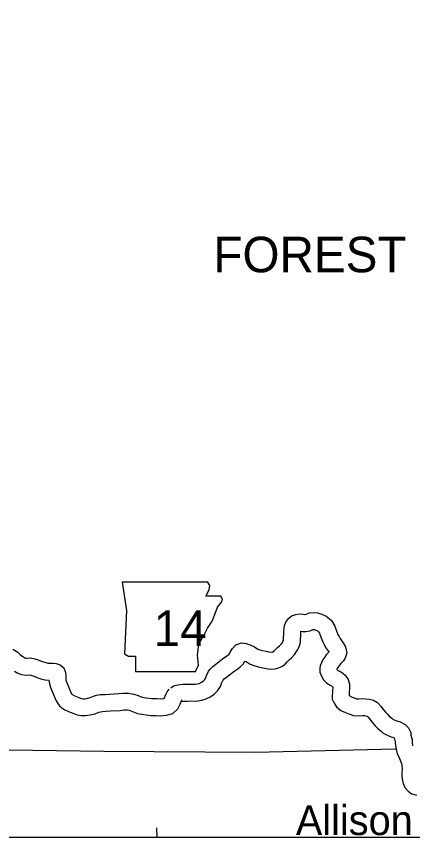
# Model space of a CAD drawing. Extents: x 1377389 to 1380723, y 1168351 to 1170484.
# Drawn here: x 1377764.7 to 1377835.2, y 1169604.3 to 1169750.4 of the extents above; entities that cross this region are included whole.
import ezdxf

# ---------------------------------------------------------------- set-up
doc = ezdxf.new("R2010")
doc.units = 0
doc.layers.add('B_Fill', color=7, linetype='Continuous')
doc.layers.add('B_Text', color=7, linetype='Continuous')

msp = doc.modelspace()

# ---------------------------------------------------------------- linework, layer by layer
at = {"layer": 'B_Fill'}
msp.add_line((1377789.75, 1169604.28), (1377789.7, 1169606.04), dxfattribs=at)
msp.add_lwpolyline([(1377783.57, 1169649.76), (1377784.33, 1169644.68), (1377783.99, 1169636.98), (1377784.67, 1169636.56), (1377785.94, 1169636.56), (1377785.94, 1169633.85), (1377796.6, 1169633.85), (1377797.11, 1169634.95), (1377796.94, 1169636.73), (1377797.19, 1169638.76), (1377798.12, 1169640.37), (1377798.71, 1169641.55), (1377799.56, 1169642.82), (1377800.07, 1169644.17), (1377800.49, 1169645.27), (1377801.25, 1169646.2), (1377801.42, 1169646.8), (1377801.08, 1169647.22), (1377798.46, 1169647.22), (1377799.05, 1169648.4), (1377799.14, 1169649.16), (1377798.78, 1169649.75)], close=True, dxfattribs=at)
for points in [[(1377792.23, 1169630.95), (1377792.71, 1169631.29), (1377793.48, 1169631.48), (1377794.34, 1169631.56), (1377795.06, 1169631.56), (1377795.9, 1169631.59), (1377796.56, 1169631.58), (1377796.98, 1169631.65), (1377797.23, 1169631.73), (1377797.69, 1169631.94), (1377797.99, 1169632.13), (1377798.17, 1169632.33), (1377798.35, 1169632.57), (1377798.49, 1169632.96), (1377798.65, 1169633.35), (1377798.93, 1169633.88), (1377799.26, 1169634.3), (1377799.69, 1169634.73), (1377800.23, 1169635.17), (1377801.39, 1169636.08), (1377802.35, 1169636.76), (1377802.56, 1169636.93), (1377802.73, 1169637.09), (1377802.85, 1169637.42), (1377803.16, 1169637.96), (1377803.78, 1169638.58), (1377804.76, 1169638.93), (1377805.61, 1169638.85), (1377806.35, 1169638.56), (1377807.09, 1169638.22), (1377807.7, 1169637.82), (1377808.04, 1169637.7), (1377808.5, 1169637.57), (1377809.15, 1169637.45), (1377809.65, 1169637.36), (1377810.1, 1169637.29), (1377810.3, 1169637.31), (1377810.48, 1169637.35), (1377810.5, 1169637.36), (1377810.6, 1169637.5), (1377810.91, 1169637.81), (1377811.21, 1169638.1), (1377811.55, 1169638.41), (1377811.91, 1169638.79), (1377812.06, 1169639.02), (1377812.16, 1169639.18), (1377812.25, 1169639.38), (1377812.27, 1169639.47), (1377812.34, 1169640.87), (1377812.37, 1169641.6), (1377812.44, 1169642.04), (1377812.7, 1169642.76), (1377813.2, 1169643.33), (1377813.77, 1169643.78), (1377814.44, 1169643.98), (1377815.09, 1169644.1), (1377815.76, 1169644.02), (1377816.07, 1169643.96), (1377816.1, 1169643.96), (1377816.3, 1169644.05), (1377816.88, 1169644.25), (1377817.57, 1169644.31), (1377818.3, 1169644.27), (1377819.09, 1169644.02), (1377819.83, 1169643.69), (1377820.35, 1169643.25), (1377820.81, 1169642.9), (1377821.38, 1169641.91), (1377821.56, 1169641.38), (1377821.72, 1169640.91), (1377821.94, 1169640.43), (1377822.14, 1169640.04), (1377822.31, 1169639.7), (1377822.55, 1169639.37), (1377822.87, 1169638.93), (1377823.3, 1169638.24), (1377823.55, 1169637.18), (1377823.2, 1169636.23), (1377822.86, 1169635.69), (1377822.46, 1169635.24), (1377822.23, 1169634.98), (1377822.04, 1169634.7), (1377821.83, 1169634.36), (1377821.75, 1169634.21), (1377821.79, 1169634.15), (1377821.84, 1169634.1), (1377821.94, 1169634.04), (1377822.3, 1169633.88), (1377822.79, 1169633.53), (1377823.2, 1169633.17), (1377823.74, 1169632.4), (1377823.99, 1169631.6), (1377824.02, 1169630.83), (1377823.95, 1169630.21)], [(1377794.24, 1169628.77), (1377793.98, 1169628.51), (1377793.98, 1169628.51), (1377794.48, 1169628.56), (1377795.11, 1169628.56), (1377795.94, 1169628.59), (1377796.79, 1169628.58), (1377797.69, 1169628.73), (1377798.3, 1169628.93), (1377799.13, 1169629.3), (1377799.93, 1169629.82), (1377800.49, 1169630.42), (1377801.02, 1169631.15), (1377801.28, 1169631.86), (1377801.38, 1169632.09), (1377801.45, 1169632.24), (1377801.52, 1169632.31), (1377801.71, 1169632.51), (1377802.09, 1169632.82), (1377803.18, 1169633.67), (1377804.16, 1169634.36), (1377804.53, 1169634.67), (1377805.07, 1169635.17), (1377805.4, 1169635.69), (1377805.64, 1169635.59), (1377806.34, 1169635.12), (1377807.13, 1169634.84), (1377807.82, 1169634.65), (1377808.6, 1169634.5), (1377809.17, 1169634.39), (1377810.02, 1169634.27), (1377810.76, 1169634.34), (1377811.36, 1169634.47), (1377811.97, 1169634.71), (1377812.57, 1169635.12), (1377812.88, 1169635.53), (1377813.03, 1169635.68), (1377813.26, 1169635.91), (1377813.66, 1169636.26), (1377814.28, 1169636.93), (1377814.58, 1169637.38), (1377814.83, 1169637.78), (1377815.09, 1169638.39), (1377815.26, 1169639), (1377815.33, 1169640.73), (1377815.35, 1169641.04), (1377815.66, 1169640.98), (1377816.23, 1169640.94), (1377816.97, 1169641.07), (1377817.38, 1169641.25), (1377817.5, 1169641.29), (1377817.64, 1169641.3), (1377817.76, 1169641.3), (1377818.02, 1169641.21), (1377818.22, 1169641.12), (1377818.47, 1169640.91), (1377818.51, 1169640.89), (1377818.64, 1169640.66), (1377818.73, 1169640.4), (1377818.93, 1169639.81), (1377819.23, 1169639.14), (1377819.47, 1169638.67), (1377819.75, 1169638.13), (1377820.11, 1169637.62), (1377820.32, 1169637.34), (1377820.23, 1169637.25), (1377819.84, 1169636.82), (1377819.52, 1169636.32), (1377819.21, 1169635.83), (1377818.93, 1169635.27), (1377818.79, 1169634.82), (1377818.73, 1169634.43), (1377818.74, 1169633.73), (1377818.99, 1169633), (1377819.37, 1169632.33), (1377819.95, 1169631.75), (1377820.53, 1169631.38), (1377820.8, 1169631.26), (1377820.91, 1169631.18), (1377820.96, 1169631.14), (1377821.01, 1169631.07), (1377821.01, 1169630.94), (1377820.97, 1169630.55)], [(1377764.13, 1169637.83), (1377764.97, 1169637.27), (1377765.41, 1169636.88), (1377765.77, 1169636.59), (1377765.99, 1169636.43), (1377766.25, 1169636.29), (1377766.44, 1169636.22), (1377766.58, 1169636.19), (1377767.26, 1169636.25), (1377768.01, 1169636.08), (1377768.59, 1169635.93), (1377769.04, 1169635.76), (1377769.54, 1169635.55), (1377769.99, 1169635.42), (1377770.3, 1169635.35), (1377770.64, 1169635.32), (1377770.96, 1169635.33), (1377771.33, 1169635.33), (1377771.83, 1169635.29), (1377772.53, 1169635.02), (1377773.18, 1169634.47), (1377773.5, 1169633.68), (1377773.53, 1169633.07), (1377773.53, 1169632.68), (1377773.52, 1169632.43), (1377773.54, 1169632.32), (1377773.64, 1169631.99), (1377774.48, 1169629.98), (1377774.56, 1169629.85), (1377774.57, 1169629.83), (1377774.64, 1169629.78), (1377774.85, 1169629.63), (1377775.44, 1169629.38), (1377775.99, 1169629.17), (1377776.32, 1169629.04), (1377776.58, 1169629), (1377776.85, 1169628.99), (1377777.27, 1169629.06), (1377777.86, 1169629.2), (1377778.43, 1169629.42), (1377779.01, 1169629.6), (1377779.71, 1169629.75), (1377780.53, 1169629.76), (1377781.29, 1169629.82), (1377782.98, 1169629.92), (1377783.74, 1169629.98), (1377784.7, 1169630.01), (1377785.62, 1169629.82), (1377786.42, 1169629.54), (1377787.1, 1169629.28), (1377787.83, 1169629.14), (1377788.83, 1169629.03), (1377789.77, 1169629.02), (1377790.38, 1169628.97), (1377790.91, 1169629.02), (1377791.02, 1169629.05), (1377791.09, 1169629.18), (1377791.25, 1169629.62), (1377791.58, 1169630.25), (1377791.92, 1169630.67)], [(1377764.38, 1169633.9), (1377765, 1169633.54), (1377765.62, 1169633.33), (1377766.39, 1169633.16), (1377767.07, 1169633.22), (1377767.31, 1169633.16), (1377767.67, 1169633.07), (1377767.91, 1169632.98), (1377768.53, 1169632.72), (1377769.27, 1169632.5), (1377769.86, 1169632.38), (1377770.5, 1169632.32), (1377770.61, 1169631.65), (1377770.81, 1169630.98), (1377771.79, 1169628.62), (1377772.08, 1169628.16), (1377772.41, 1169627.72), (1377772.83, 1169627.38), (1377773.37, 1169627), (1377774.31, 1169626.59), (1377774.94, 1169626.36), (1377775.53, 1169626.14), (1377776.27, 1169626.01), (1377777.03, 1169625.98), (1377777.86, 1169626.11), (1377778.77, 1169626.33), (1377779.41, 1169626.59), (1377779.76, 1169626.69), (1377780.04, 1169626.75), (1377780.68, 1169626.76), (1377781.5, 1169626.83), (1377783.19, 1169626.92), (1377783.92, 1169626.99), (1377784.44, 1169627), (1377784.82, 1169626.93), (1377785.38, 1169626.73), (1377786.27, 1169626.38), (1377787.39, 1169626.17), (1377788.65, 1169626.03), (1377789.63, 1169626.02), (1377790.39, 1169625.95), (1377791.46, 1169626.06), (1377792.57, 1169626.37), (1377793.45, 1169627.2), (1377793.85, 1169628), (1377794, 1169628.41), (1377794.09, 1169628.58), (1377794.24, 1169628.77)], [(1377820.97, 1169630.55), (1377820.95, 1169630.03), (1377820.92, 1169629.7), (1377820.91, 1169628.92), (1377821.29, 1169628.18), (1377821.7, 1169627.56), (1377822.48, 1169626.91), (1377823.27, 1169626.56), (1377823.9, 1169626.28), (1377824.72, 1169626.01), (1377825.67, 1169625.97), (1377826.3, 1169626.01), (1377826.64, 1169626), (1377826.91, 1169625.95), (1377827.13, 1169625.9), (1377827.31, 1169625.7), (1377827.56, 1169625.4), (1377828.14, 1169624.67), (1377828.59, 1169624.18), (1377828.98, 1169623.73), (1377829.6, 1169623.23), (1377830, 1169622.88), (1377830.71, 1169622.49), (1377831.42, 1169622.24), (1377831.84, 1169622.09), (1377831.92, 1169622.05), (1377832.13, 1169621.35), (1377832.12, 1169621.02), (1377832.28, 1169620.01), (1377832.49, 1169619.19), (1377832.77, 1169618.64), (1377833.22, 1169617.48), (1377833.3, 1169617.19), (1377833.32, 1169617.01), (1377833.35, 1169616.62), (1377833.37, 1169616.27), (1377833.33, 1169615.9), (1377833.32, 1169615.35), (1377833.35, 1169614.7), (1377833.53, 1169613.92), (1377833.86, 1169613.18), (1377834.45, 1169612.55), (1377835.08, 1169612.08), (1377835.94, 1169611.86)], [(1377823.96, 1169630.34), (1377823.95, 1169629.87), (1377823.93, 1169629.63), (1377823.96, 1169629.58), (1377824.07, 1169629.49), (1377824.49, 1169629.3), (1377824.98, 1169629.08), (1377825.26, 1169628.99), (1377825.65, 1169628.97), (1377826.22, 1169629.01), (1377826.93, 1169629), (1377827.54, 1169628.89), (1377828.25, 1169628.71), (1377828.97, 1169628.32), (1377829.57, 1169627.68), (1377829.89, 1169627.28), (1377830.42, 1169626.62), (1377830.83, 1169626.18), (1377831.07, 1169625.89), (1377831.51, 1169625.54), (1377831.73, 1169625.35), (1377831.95, 1169625.23), (1377832.4, 1169625.07), (1377833.02, 1169624.86), (1377833.87, 1169624.42), (1377834.49, 1169623.81), (1377834.91, 1169622.99), (1377834.92, 1169622.49), (1377835.14, 1169621.75), (1377835.13, 1169621.22), (1377835.22, 1169620.63)], [(1377753.61, 1169620.04), (1377754.94, 1169620.01), (1377780.32, 1169619.66), (1377807.22, 1169619.47), (1377832.15, 1169620.09)]]:
    msp.add_lwpolyline(points, dxfattribs=at)
at = {"layer": 'B_Text'}
msp.add_lwpolyline([(1377549.76, 1170388.77), (1378279.16, 1170388.77), (1378279.16, 1169604.28), (1377549.76, 1169604.28)], close=True, dxfattribs=at)

# ---------------------------------------------------------------- texts
at = {"layer": 'B_Fill'}
for s, height, p in [('FOREST', 6.336, (1377799.78, 1169704.88)), ('14', 6.336, (1377789.15, 1169638.37)), ('Allison', 5.28, (1377814.45, 1169604.73))]:
    msp.add_text(s, height=height, dxfattribs=at).set_placement(p)

doc.saveas('drawing.dxf')
